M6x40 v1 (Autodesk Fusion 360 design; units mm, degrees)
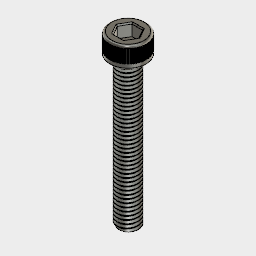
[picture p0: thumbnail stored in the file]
sketch "スケッチ1"
  circle C1 centre (0, 0) radius 3
  circle C2 centre (0, 0) radius 5
  dimension "d1" diameter C1 = 6
  dimension "d2" diameter C2 = 10
extrude "押し出し1" new body sketch "スケッチ1" blind 5.8
sketch "スケッチ2" plane through (0, 0, 5.8) normal (0, 0, 1) x axis (-1, 0, 0)
  line L1 (-1.4722, -2.55) -> (-2.9445, 0)
  line L2 (1.4722, -2.55) -> (-1.4722, -2.55)
  line L3 (2.9445, 0) -> (1.4722, -2.55)
  line L4 (1.4722, 2.55) -> (2.9445, 0)
  line L5 (-1.4722, 2.55) -> (1.4722, 2.55)
  line L6 (-2.9445, 0) -> (-1.4722, 2.55)
  circle C1 centre (0, 0) radius 5
  dimension "d5" distance L2 L5 = 5.1
work_plane "作業平面" sketch "スケッチ2" AlongDistance -0.75
extrude "押し出し2" cut sketch "スケッチ2" profile of L1 L2 L3 L4 L5 L6 against normal blind 3.3
chamfer "面取り" distance 0.3
sketch "スケッチ3" plane through (0, 0, 5.05) normal (0, 0, 1) x axis (1, 0, 0)
  line L1 (-0.05, 4.9497) -> (-0.05, 4.9997)
  line L2 (0.05, 4.9497) -> (-0.05, 4.9497)
  line L3 (0.05, 4.9997) -> (0.05, 4.9497)
  circle C1 centre (0, 0) radius 5
  point P4 (-0.05, 4.9497)
  point P5 (0.05, 4.9497)
  point P3 (-0.05, 4.9997)
  point P6 (0.05, 4.9997)
  dimension "d18" distance P4 P5 = 0.1
  dimension "d19" distance P3 P4 = 0.05
  dimension "d20" distance P5 P6 = 0.05 (= "d19")
extrude "押し出し3" cut sketch "スケッチ3" against normal blind 3.6
work_axis "作業軸"
circular_pattern "C パターン" countU 100 TotalAngle 360
fillet "フィレット1" radius 0.6
extrude "押し出し4" add sketch "スケッチ1" profile of C1 blind -40
thread "ねじ"
fillet "フィレット2" sketch "スケッチ3" radius 0.5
